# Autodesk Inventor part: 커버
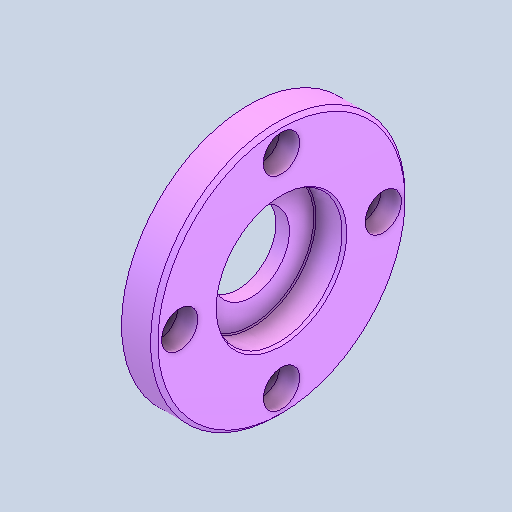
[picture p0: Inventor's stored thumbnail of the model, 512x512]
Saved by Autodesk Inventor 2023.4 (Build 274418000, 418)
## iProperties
Created: 2024-09
Part Number: 커버
Material: 알루미늄 6061
Document SubType Name: Modeling
Designer: 11
Density: 2.7 g/cm^3
Appearance: 기본값
Author: jhkim
Sending System: Autodesk Inventor 2025
Preprocessor: ST-DEVELOPER v20
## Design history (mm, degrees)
node "커버1"
node "솔리드2"
node "솔리드1"
